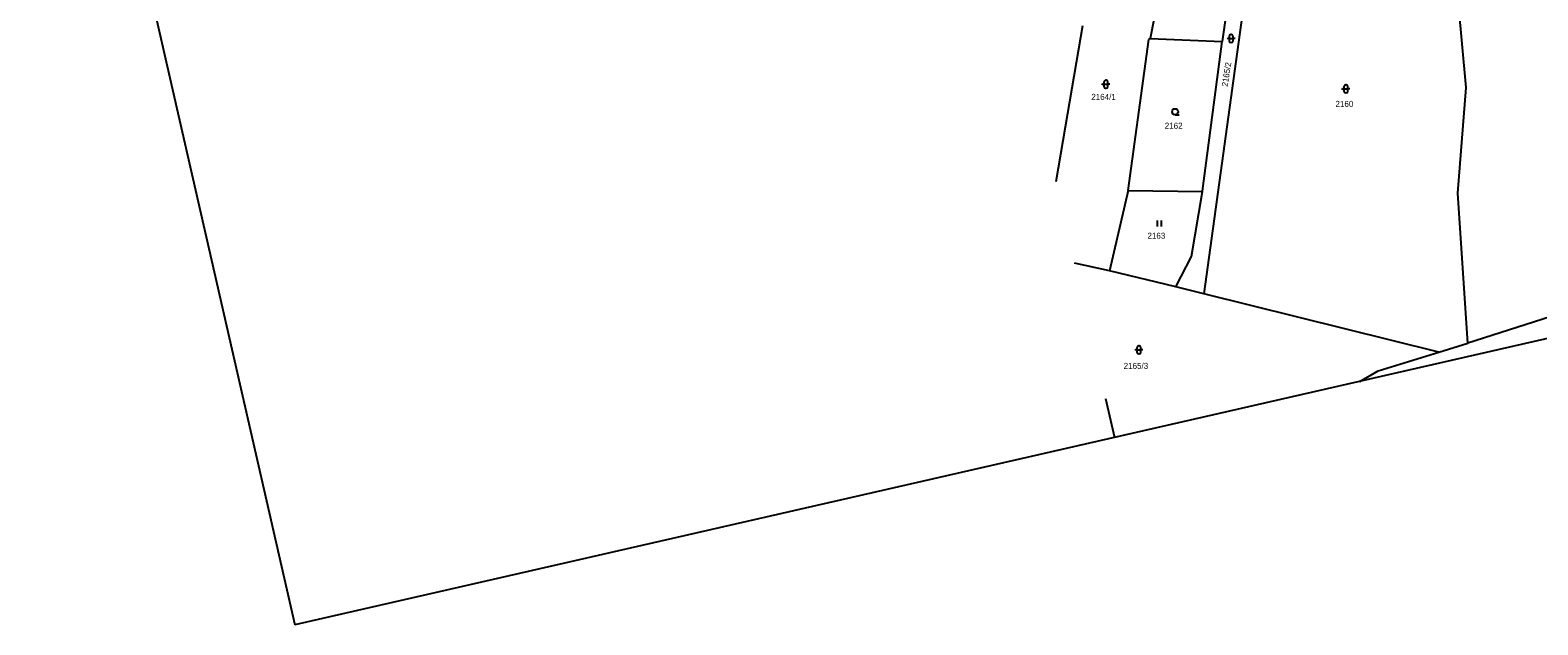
# Model space of a CAD drawing. Extents: x -805730 to -804640, y -1150889 to -1150366.
# Drawn here: x -805730.2 to -805353.5, y -1150889.4 to -1150740.9 of the extents above; entities that cross this region are included whole.
import ezdxf

# ---------------------------------------------------------------- set-up
doc = ezdxf.new("R2010")
doc.units = 0
for name, color, linetype in [('Default', 7, 'Continuous'), ('formát', 7, 'Continuous'), ('kn_celek - Cisla pozemkovych parcel', 7, 'Continuous'), ('kn_celek - Hranice parcel', 7, 'Continuous'), ('kn_celek - Znacky kultur', 7, 'Continuous')]:
    doc.layers.add(name, color=color, linetype=linetype)

# ---------------------------------------------------------------- blocks, each defined once
blk = doc.blocks.new('316')
at = {"layer": 'Default'}
for p, q in [((-8.3, 10), (-10, 8.1)), ((-5, 10), (-8.3, 10)), ((-5, 15.5), (-5, 4.5)), ((-5, 10), (5, 10)), ((0.5, 20), (-0.5, 20)), ((-0.5, 0), (0.5, 0)), ((5, 4.5), (5, 15.5)), ((10, 10), (5, 10))]:
    blk.add_line(p, q, dxfattribs=at)
for centre, start, end in [((-0.5, 15.5), 90, 180), ((-0.5, 4.5), 180, 270), ((0.5, 15.5), 0, 90), ((0.5, 4.5), 270, 0)]:
    blk.add_arc(centre, 4.5, start, end, dxfattribs=at)
blk = doc.blocks.new('304')
at = {"layer": 'Default'}
blk.add_line((-0.1, 0), (9.9, 0), dxfattribs=at)
blk.add_circle((-0.1, 7.5), 7.5, dxfattribs=at)
blk = doc.blocks.new('306')
at = {"layer": 'Default'}
for p, q in [((-5.2, 0), (-5.2, 15)), ((4.8, 0), (4.8, 15))]:
    blk.add_line(p, q, dxfattribs=at)

msp = doc.modelspace()

# ---------------------------------------------------------------- linework, layer by layer
at = {"layer": 'formát'}
for p, q in [((-805730.21, -1150599.91), (-805664.04, -1150889.45)), ((-805049.87, -1150749.08), (-805664.04, -1150889.45)), ((-805461.54, -1150832.91), (-805459.31, -1150842.66))]:
    msp.add_line(p, q, dxfattribs=at)
at = {"layer": 'kn_celek - Hranice parcel'}
for p, q in [((-805424.25, -1150714.35), (-805436.99, -1150806.72)), ((-805445.91, -1150720.66), (-805450.4, -1150742.95)), ((-805430.82, -1150732.62), (-805432.36, -1150743.71)), ((-805371.44, -1150755.25), (-805373.3, -1150734.28)), ((-805467.24, -1150739.8), (-805471.05, -1150761.74)), ((-805455.86, -1150780.97), (-805450.71, -1150743.25)), ((-805450.71, -1150743.25), (-805450.4, -1150742.95)), ((-805450.4, -1150742.95), (-805432.36, -1150743.71)), ((-805437.17, -1150780.43), (-805432.36, -1150743.71)), ((-805373.53, -1150781.61), (-805371.44, -1150755.25)), ((-805471.05, -1150761.74), (-805473.91, -1150778.82)), ((-805455.86, -1150780.97), (-805460.49, -1150800.98)), ((-805455.86, -1150780.97), (-805437.27, -1150781.19)), ((-805440.04, -1150797.44), (-805437.27, -1150781.19)), ((-805437.27, -1150781.19), (-805437.17, -1150780.43)), ((-805370.96, -1150819.06), (-805373.53, -1150781.61)), ((-805460.49, -1150800.98), (-805469.28, -1150799.06)), ((-805443.96, -1150804.99), (-805440.04, -1150797.44)), ((-805443.96, -1150804.99), (-805460.49, -1150800.98)), ((-805436.99, -1150806.72), (-805443.96, -1150804.99)), ((-805378.22, -1150821.3), (-805436.99, -1150806.72)), ((-805350.4, -1150812.49), (-805370.96, -1150819.06)), ((-805378.22, -1150821.3), (-805370.96, -1150819.06)), ((-805393.44, -1150826.01), (-805378.22, -1150821.3)), ((-805397.96, -1150828.63), (-805393.44, -1150826.01))]:
    msp.add_line(p, q, dxfattribs=at)

# ---------------------------------------------------------------- block references
at = {"layer": 'kn_celek - Znacky kultur', "xscale": 0.1, "yscale": 0.10000000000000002}
for name, p in [('316', (-805430.16, -1150743.99)), ('316', (-805461.44, -1150755.42)), ('316', (-805401.47, -1150756.57)), ('304', (-805444.13, -1150762.02)), ('306', (-805448.01, -1150789.96)), ('316', (-805453.17, -1150821.76))]:
    msp.add_blockref(name, p, dxfattribs=at)

# ---------------------------------------------------------------- texts
at = {"layer": 'kn_celek - Cisla pozemkovych parcel'}
msp.add_text('2165/2', height=1.5, rotation=81, dxfattribs=at).set_placement((-805431.03, -1150755.09))
for s, p in [('2164/1', (-805465.08, -1150758.3)), ('2160', (-805404.07, -1150760.06)), ('2162', (-805446.73, -1150765.51)), ('2163', (-805451.05, -1150793)), ('2165/3', (-805457, -1150825.51))]:
    msp.add_text(s, height=1.5, dxfattribs=at).set_placement(p)

doc.saveas('drawing.dxf')
